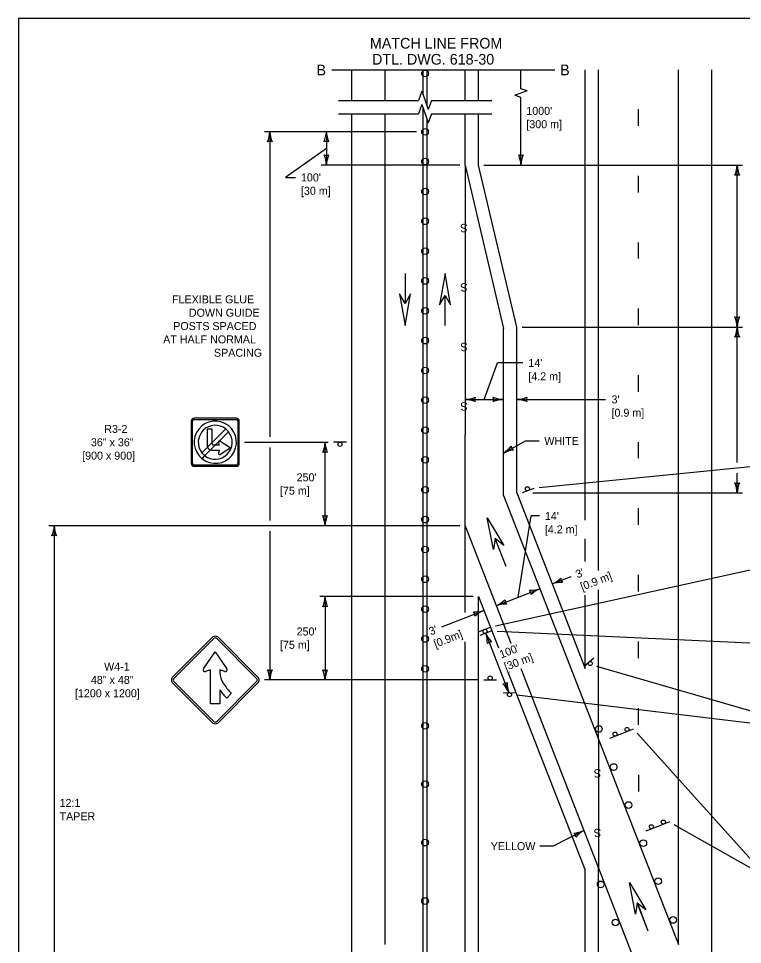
# Model space of a CAD drawing. Extents: x 49991.4 to 50021, y 49987.6 to 50011.4.
# Drawn here: x 50000.34 to 50005.76, y 50004.32 to 50011.26 of the extents above; entities that cross this region are included whole.
import ezdxf

# ---------------------------------------------------------------- set-up
doc = ezdxf.new("R2010")
doc.units = 0
for name, color, linetype in [('Level 1', 7, 'Continuous'), ('Level 2', 7, 'Continuous'), ('Level 3', 7, 'Continuous'), ('Level 6', 7, 'Continuous')]:
    doc.layers.add(name, color=color, linetype=linetype)

msp = doc.modelspace()

# ---------------------------------------------------------------- linework, layer by layer
at = {"layer": 'Level 1'}
for p, q in [((50002.8337, 50010.6493), (50002.8337, 50010.8774)), ((50003.0837, 50010.6493), (50003.0837, 50010.8774)), ((50003.3688, 50010.6919), (50003.3688, 50010.8773)), ((50003.3988, 50010.6067), (50003.3988, 50010.8773)), ((50003.6838, 50010.6493), (50003.6838, 50010.8773)), ((50003.7838, 50010.6493), (50003.7838, 50010.8773)), ((50004.5838, 50007.5049), (50004.5838, 50010.8773)), ((50004.6837, 50007.1256), (50004.6837, 50010.8774)), ((50005.2837, 50004.324), (50005.2837, 50010.8774)), ((50005.5337, 50003.9574), (50005.5337, 50010.8774)), ((50003.3688, 50002.0911), (50003.3688, 50010.5919)), ((50004.9837, 50010.4593), (50004.9837, 50010.5843)), ((50002.8337, 50003.9575), (50002.8337, 50010.5493)), ((50003.0837, 50004.324), (50003.0837, 50010.5493)), ((50003.3988, 50002.0911), (50003.3988, 50010.5067)), ((50003.6838, 50010.1642), (50003.6838, 50010.5493)), ((50003.7838, 50010.1642), (50003.7838, 50010.5493)), ((50003.6838, 50010.1642), (50003.6838, 50008.1421)), ((50003.6838, 50010.1642), (50003.9712, 50008.9389)), ((50004.0712, 50008.9505), (50003.7838, 50010.1642)), ((50004.9837, 50009.9592), (50004.9837, 50010.0843)), ((50004.9837, 50009.4642), (50004.9837, 50009.5842)), ((50003.2337, 50009.3525), (50003.2337, 50009.1267)), ((50003.2339, 50009.3525), (50003.2339, 50009.1267)), ((50003.5336, 50008.9625), (50003.5336, 50009.1883)), ((50003.5338, 50008.9625), (50003.5338, 50009.1883)), ((50004.9837, 50008.9642), (50004.9837, 50009.0892)), ((50003.9712, 50007.6888), (50003.9712, 50008.9389)), ((50004.0712, 50007.7075), (50004.0712, 50008.9505)), ((50004.9837, 50008.4642), (50004.9837, 50008.5892)), ((50001.6305, 50008.2449), (50001.6305, 50007.93)), ((50001.6399, 50007.93), (50001.6399, 50008.2449)), ((50001.968, 50008.2674), (50001.653, 50008.2674)), ((50001.653, 50008.258), (50001.968, 50008.258)), ((50001.9811, 50008.2449), (50001.9811, 50007.9299)), ((50001.9905, 50007.9299), (50001.9905, 50008.2449)), ((50001.7104, 50008.0084), (50001.8894, 50008.1875)), ((50001.9106, 50008.1663), (50001.7316, 50007.9872)), ((50001.788, 50008.1849), (50001.7505, 50008.1849)), ((50001.7505, 50008.1849), (50001.7505, 50008.0614)), ((50001.788, 50008.0776), (50001.788, 50008.1849)), ((50001.8894, 50008.1875), (50001.9106, 50008.1663)), ((50001.8894, 50008.1875), (50001.9106, 50008.1663)), ((50001.8339, 50008.0868), (50001.8408, 50008.0649)), ((50001.923, 50008.0461), (50001.8449, 50008.0954)), ((50002.7937, 50008.0873), (50002.6977, 50008.0873)), ((50003.6838, 50006.8117), (50003.6838, 50008.1421)), ((50004.9837, 50007.9691), (50004.9837, 50008.0892)), ((50001.7316, 50007.9872), (50001.7104, 50008.0084)), ((50001.7316, 50007.9872), (50001.7104, 50008.0084)), ((50001.7845, 50008.0274), (50001.8408, 50008.0274)), ((50001.8408, 50008.0649), (50001.8007, 50008.0649)), ((50001.8408, 50008.0274), (50001.8339, 50008.0054)), ((50001.8449, 50007.9969), (50001.923, 50008.0461)), ((50001.7121, 50007.9639), (50001.7316, 50007.9872)), ((50001.7321, 50007.9868), (50001.7126, 50007.9635)), ((50001.8449, 50007.9969), (50001.8449, 50007.9969)), ((50001.6305, 50007.93), (50001.6399, 50007.93)), ((50001.6305, 50007.9299), (50001.6399, 50007.9299)), ((50001.6399, 50007.9299), (50001.6305, 50007.9299)), ((50001.968, 50007.9167), (50001.653, 50007.9167)), ((50001.653, 50007.9074), (50001.968, 50007.9074)), ((50004.2006, 50007.7421), (50004.1112, 50007.7075)), ((50003.9712, 50007.6888), (50005.2838, 50004.3238)), ((50004.0712, 50007.7075), (50004.5838, 50006.3931)), ((50004.9837, 50007.4692), (50004.9837, 50007.5941)), ((50003.6838, 50007.4623), (50004.0273, 50006.5815)), ((50003.9916, 50007.1565), (50003.9096, 50007.367)), ((50003.9918, 50007.1565), (50003.9098, 50007.3671)), ((50004.5838, 50007.194), (50004.5838, 50007.3649)), ((50004.9837, 50006.9691), (50004.9837, 50007.0942)), ((50004.6837, 50005.8621), (50004.6837, 50006.9812)), ((50003.7838, 50006.931), (50003.9339, 50006.5462)), ((50003.7838, 50002.0911), (50003.7838, 50006.931)), ((50004.5838, 50006.3931), (50004.5838, 50006.9423)), ((50003.7839, 50006.6673), (50003.8733, 50006.7019)), ((50001.7893, 50006.6262), (50001.4904, 50006.3273)), ((50001.7893, 50006.6262), (50001.7893, 50006.6262)), ((50002.1309, 50006.3273), (50001.832, 50006.6262)), ((50003.8837, 50006.6735), (50003.7943, 50006.6389)), ((50001.7993, 50006.6161), (50001.5004, 50006.3172)), ((50001.7993, 50006.6161), (50001.7993, 50006.6161)), ((50002.1207, 50006.3172), (50001.8219, 50006.6161)), ((50003.6838, 50002.0911), (50003.6838, 50006.593)), ((50004.9837, 50006.4691), (50004.9837, 50006.5941)), ((50001.7224, 50006.389), (50001.8106, 50006.5172)), ((50001.8106, 50006.5172), (50001.8988, 50006.389)), ((50004.5778, 50006.4097), (50004.65, 50006.4728)), ((50001.7754, 50006.3809), (50001.7376, 50006.3686)), ((50001.7754, 50006.1281), (50001.7754, 50006.3809)), ((50001.8836, 50006.3686), (50001.8457, 50006.3809)), ((50001.8457, 50006.3809), (50001.8458, 50006.3596)), ((50004.0064, 50006.3603), (50004.5838, 50004.8798)), ((50004.1009, 50006.393), (50005.2837, 50003.3608)), ((50001.4904, 50006.2845), (50001.7893, 50005.9856)), ((50001.5004, 50006.2947), (50001.7993, 50005.9958)), ((50001.8219, 50005.9958), (50002.1207, 50006.2947)), ((50001.832, 50005.9856), (50002.1309, 50006.2845)), ((50003.8238, 50006.306), (50003.9198, 50006.306)), ((50001.8458, 50006.2323), (50001.8458, 50006.1281)), ((50001.9309, 50006.2044), (50001.8965, 50006.17)), ((50003.9689, 50006.2103), (50004.0647, 50006.2122)), ((50001.8458, 50006.1281), (50001.7754, 50006.1281)), ((50004.9837, 50005.9711), (50004.9837, 50006.0941)), ((50004.8584, 50005.904), (50004.9478, 50005.9388)), ((50004.6837, 50005.8621), (50004.6838, 50004.8987)), ((50004.7689, 50005.8691), (50004.8584, 50005.904)), ((50004.9837, 50005.5961), (50004.9837, 50005.471)), ((50005.1305, 50005.2103), (50005.22, 50005.2452)), ((50005.0411, 50005.1754), (50005.1305, 50005.2103)), ((50004.6838, 50001.8518), (50004.6838, 50004.8987)), ((50004.5838, 50000.9624), (50004.5838, 50004.8798)), ((50005.0573, 50004.4244), (50004.9752, 50004.6349)), ((50005.0575, 50004.4245), (50004.9754, 50004.635))]:
    msp.add_line(p, q, dxfattribs=at)
for points in [[(50008.6146, 50011.2628), (50000.3356, 50011.2628), (50000.3356, 50000.0624), (50008.6146, 50000.0624)], [(50003.5756, 50009.1161), (50003.5338, 50009.3525), (50003.492, 50009.1161), (50003.5338, 50009.1881)], [(50003.1919, 50009.1989), (50003.2337, 50008.9625), (50003.2755, 50009.1989), (50003.2337, 50009.1269)], [(50003.8967, 50007.2845), (50003.8497, 50007.52), (50003.9746, 50007.3148), (50003.9096, 50007.3668)], [(50004.9623, 50004.5523), (50004.9154, 50004.7879), (50005.0403, 50004.5826), (50004.9752, 50004.6347)]]:
    msp.add_lwpolyline(points, close=True, dxfattribs=at)
msp.add_lwpolyline([(50001.8102, 50006.5166), (50001.8107, 50006.5171)], dxfattribs=at)
for centre, radius in [((50003.3838, 50010.8517), 0.025), ((50003.3838, 50010.4142), 0.025), ((50003.3838, 50010.1907), 0.025), ((50003.3838, 50009.9671), 0.025), ((50003.3838, 50009.7435), 0.025), ((50003.3838, 50009.52), 0.025), ((50003.3838, 50009.2964), 0.025), ((50003.3838, 50009.0729), 0.025), ((50003.3838, 50008.8493), 0.025), ((50003.3838, 50008.6257), 0.025), ((50003.3838, 50008.4022), 0.025), ((50003.3838, 50008.1786), 0.025), ((50002.7458, 50008.0721), 0.0152), ((50003.3838, 50007.9551), 0.025), ((50003.3838, 50007.7315), 0.025), ((50004.1506, 50007.739), 0.0152), ((50003.3838, 50007.5079), 0.025), ((50003.3838, 50007.2844), 0.025), ((50003.3838, 50007.0608), 0.025), ((50003.3838, 50006.8373), 0.025), ((50003.3838, 50006.6137), 0.025), ((50003.8339, 50006.6705), 0.0152), ((50003.8339, 50006.6705), 0.0152), ((50003.3838, 50006.3901), 0.025), ((50004.6236, 50006.4298), 0.0152), ((50003.8717, 50006.3211), 0.0152), ((50004.0169, 50006.1961), 0.0152), ((50003.3838, 50005.9623), 0.025), ((50004.6867, 50005.9388), 0.025), ((50004.898, 50005.9353), 0.0152), ((50004.8086, 50005.9004), 0.0152), ((50004.7979, 50005.6538), 0.025), ((50003.3838, 50005.5248), 0.025), ((50004.909, 50005.3687), 0.025), ((50005.1702, 50005.2415), 0.0152), ((50005.0807, 50005.2066), 0.0152), ((50003.3838, 50005.0873), 0.025), ((50005.0202, 50005.0837), 0.025), ((50005.1314, 50004.7987), 0.025), ((50004.7005, 50004.7745), 0.025), ((50003.3838, 50004.6498), 0.025), ((50004.8117, 50004.4894), 0.025), ((50005.2442, 50004.5079), 0.025)]:
    msp.add_circle(centre, radius, dxfattribs=at)
for centre, radius, start, end in [((50001.6531, 50008.2448), 0.0225, 90, 180), ((50001.6531, 50008.2448), 0.0131, 90, 180), ((50001.811, 50008.0878), 0.1585, 231.65928, 231.42697), ((50001.8106, 50008.0873), 0.1275, 51.75713, 218.2435), ((50001.9681, 50008.2448), 0.0225, 0, 90), ((50001.9681, 50008.2448), 0.0131, 0, 90), ((50001.8106, 50008.0873), 0.1275, 139.12855, 139.14364), ((50001.8106, 50008.0873), 0.1275, 232.04534, 38.24287), ((50001.8008, 50008.0776), 0.0128, 180, 270), ((50001.841, 50008.089), 0.00742, 57.75616, 197.61961), ((50001.7846, 50008.0613), 0.034, 180, 270), ((50001.841, 50008.0031), 0.00742, 162.38136, 302.24299), ((50001.8106, 50008.0873), 0.1275, 315.58365, 315.71312), ((50001.6531, 50007.9298), 0.0225, 180, 270), ((50001.6531, 50007.9298), 0.0131, 180, 270), ((50001.9681, 50007.9298), 0.0225, 270, 0), ((50001.9681, 50007.9298), 0.0131, 270, 0), ((50001.8106, 50006.6048), 0.0302, 45.00008, 134.99993), ((50001.8106, 50006.6048), 0.0159, 45.00008, 134.99993), ((50001.7334, 50006.3814), 0.0134, 145.48059, 287.95818), ((50001.975, 50006.3596), 0.1292, 180, 216.3165), ((50001.8878, 50006.3814), 0.0134, 252.04182, 34.51941), ((50001.5117, 50006.3059), 0.0302, 134.99993, 225.00008), ((50001.5117, 50006.3059), 0.0159, 134.99993, 225.00008), ((50002.2576, 50006.5156), 0.4512, 211.01433, 223.6035), ((50002.1095, 50006.3059), 0.0159, 314.99993, 45.00007), ((50002.1095, 50006.3059), 0.0302, 314.99993, 45.00008), ((50002.2576, 50006.5156), 0.4999, 214.53029, 223.73943), ((50001.8106, 50006.007), 0.0159, 225.00007, 314.99993), ((50001.8106, 50006.007), 0.0302, 225.00007, 314.99993)]:
    msp.add_arc(centre, radius, start, end, dxfattribs=at)
at = {"layer": 'Level 3'}
for p, q in [((50004.1029, 50010.7364), (50004.1029, 50010.8773)), ((50004.1487, 50010.7202), (50004.1029, 50010.7364)), ((50004.1487, 50010.7202), (50004.1029, 50010.704)), ((50004.1029, 50010.704), (50004.0573, 50010.6878)), ((50004.1029, 50010.6716), (50004.0573, 50010.6878)), ((50004.1029, 50010.1642), (50004.1029, 50010.6716)), ((50003.3188, 50010.4142), (50002.1797, 50010.4142)), ((50002.2197, 50010.4142), (50002.2197, 50008.1273)), ((50002.6437, 50010.4142), (50002.6437, 50010.1642)), ((50003.6438, 50010.1642), (50002.6037, 50010.1642)), ((50003.8238, 50010.1642), (50005.7637, 50010.1642)), ((50005.7237, 50008.9505), (50005.7237, 50010.1642)), ((50004.1112, 50008.9505), (50005.7637, 50008.9505)), ((50005.7237, 50007.9368), (50005.7237, 50008.9505)), ((50003.8275, 50008.4088), (50003.9267, 50008.6816)), ((50004.1181, 50008.6816), (50003.9267, 50008.6816)), ((50003.6838, 50008.4088), (50003.9712, 50008.4088)), ((50004.0712, 50008.4088), (50004.7357, 50008.4088)), ((50002.0306, 50008.0874), (50002.6577, 50008.0873)), ((50002.6337, 50007.4623), (50002.6337, 50008.0873)), ((50003.9712, 50008.0066), (50004.1381, 50008.0972)), ((50004.1381, 50008.0972), (50004.2381, 50008.0972)), ((50002.2197, 50008.0473), (50002.2197, 50007.5023)), ((50004.2401, 50007.7482), (50006.2164, 50007.9462)), ((50005.7237, 50007.7075), (50005.7237, 50007.8568)), ((50004.1912, 50007.7075), (50005.7637, 50007.7075)), ((50004.0808, 50006.9261), (50004.1796, 50007.5349)), ((50004.2422, 50007.5349), (50004.1796, 50007.5349)), ((50003.6438, 50007.4623), (50000.5634, 50007.4623)), ((50000.6034, 50007.4623), (50000.6034, 50003.3608)), ((50002.2197, 50007.4223), (50002.2197, 50006.306)), ((50003.9122, 50006.711), (50006.3662, 50007.2512)), ((50004.3366, 50007.0256), (50004.4782, 50007.0806)), ((50003.9177, 50006.8627), (50004.2438, 50006.9895)), ((50003.7438, 50006.931), (50002.5937, 50006.931)), ((50002.6337, 50006.931), (50002.6337, 50006.306)), ((50003.5087, 50006.7036), (50003.8244, 50006.8264)), ((50004.0112, 50006.2111), (50003.8392, 50006.6563)), ((50003.9236, 50006.6717), (50006.2162, 50006.5656)), ((50006.3646, 50005.917), (50004.6718, 50006.4062)), ((50003.7838, 50006.306), (50002.1797, 50006.306)), ((50006.3646, 50005.917), (50004.0718, 50006.1913)), ((50005.9453, 50004.8292), (50004.9734, 50005.9081)), ((50004.5743, 50005.1792), (50004.3446, 50005.0608)), ((50005.9453, 50004.8292), (50005.2517, 50005.2208)), ((50004.3446, 50005.0608), (50004.2446, 50005.0608))]:
    msp.add_line(p, q, dxfattribs=at)
msp.add_lwpolyline([(50002.6437, 50010.2892), (50002.3386, 50010.072), (50002.4134, 50010.072)], dxfattribs=at)
for centre, radius, start, end in [((50001.987, 50010.4257), 0.233, 337.92284, 357.17269), ((50002.4418, 50010.4234), 0.2223, 182.36048, 202.54399), ((50002.411, 50010.4257), 0.233, 337.92284, 357.17269), ((50002.8658, 50010.4234), 0.2223, 182.36048, 202.54399), ((50002.2197, 50010.286), 0.0548, 72.13882, 107.86118), ((50002.6437, 50010.286), 0.0548, 72.13882, 107.86118), ((50002.4216, 50010.155), 0.2223, 2.36048, 22.54399), ((50002.6437, 50010.2924), 0.0548, 252.13882, 287.86118), ((50002.8764, 50010.1527), 0.233, 157.92284, 177.17269), ((50004.1029, 50010.2925), 0.0548, 252.13882, 287.86118), ((50003.8702, 50010.1527), 0.233, 2.82731, 22.07716), ((50004.325, 50010.1551), 0.2223, 157.45601, 177.63952), ((50005.491, 50010.1757), 0.233, 337.92284, 357.17269), ((50005.9458, 50010.1734), 0.2223, 182.36048, 202.54399), ((50005.7237, 50010.036), 0.0548, 72.13882, 107.86118), ((50005.5016, 50008.9414), 0.2223, 2.36048, 22.54399), ((50005.7237, 50009.0788), 0.0548, 252.13882, 287.86118), ((50005.9564, 50008.939), 0.233, 157.92284, 177.17269), ((50005.491, 50008.962), 0.233, 337.92284, 357.17269), ((50005.9458, 50008.9597), 0.2223, 182.36048, 202.54399), ((50005.7237, 50008.8223), 0.0548, 72.13882, 107.86118), ((50003.6723, 50008.6415), 0.233, 272.82731, 292.07716), ((50003.812, 50008.4088), 0.0548, 162.13882, 197.86118), ((50003.843, 50008.4088), 0.0548, 342.13882, 17.86118), ((50003.9827, 50008.6415), 0.233, 247.92284, 267.17269), ((50004.0597, 50008.6415), 0.233, 272.82731, 292.07716), ((50004.1994, 50008.4088), 0.0548, 162.13882, 197.86118), ((50003.6746, 50008.1867), 0.2223, 67.45601, 87.63952), ((50003.9803, 50008.1867), 0.2223, 92.36048, 112.54399), ((50004.062, 50008.1867), 0.2223, 67.45601, 87.63952), ((50002.4116, 50008.0965), 0.2223, 337.45601, 357.63952), ((50002.8664, 50008.0988), 0.233, 182.82731, 202.07716), ((50002.6337, 50007.9591), 0.0548, 72.13882, 107.86118), ((50003.8501, 50008.2056), 0.233, 301.32055, 320.5704), ((50004.0691, 50007.807), 0.2223, 95.94925, 116.13275), ((50004.0839, 50008.0677), 0.0548, 190.63205, 226.35442), ((50005.5016, 50007.6983), 0.2223, 2.36048, 22.54399), ((50005.7237, 50007.8357), 0.0548, 252.13882, 287.86118), ((50005.9564, 50007.696), 0.233, 157.92284, 177.17269), ((50002.6337, 50007.5905), 0.0548, 252.13882, 287.86118), ((50002.401, 50007.4508), 0.233, 2.82731, 22.07716), ((50002.8558, 50007.4531), 0.2223, 157.45601, 177.63952), ((50000.3813, 50007.4715), 0.2223, 337.45601, 357.63952), ((50000.8362, 50007.4738), 0.233, 182.82731, 202.07716), ((50000.6034, 50007.3341), 0.0548, 72.13882, 107.86118), ((50004.2413, 50007.2382), 0.233, 294.13681, 313.38666), ((50004.4088, 50006.8153), 0.2223, 88.76551, 108.94902), ((50004.456, 50007.0722), 0.0548, 183.44832, 219.17068), ((50004.1733, 50007.2116), 0.233, 268.36713, 287.61698), ((50004.1237, 50006.9447), 0.0548, 2.58311, 38.30547), ((50004.33, 50006.7846), 0.2223, 112.80477, 132.98828), ((50002.4116, 50006.9402), 0.2223, 337.45601, 357.63952), ((50002.8664, 50006.9425), 0.233, 182.82731, 202.07716), ((50003.8224, 50007.0753), 0.233, 294.13681, 313.38666), ((50004.0371, 50006.9093), 0.0548, 183.44832, 219.17068), ((50002.6337, 50006.8028), 0.0548, 72.13882, 107.86118), ((50003.7539, 50007.0485), 0.233, 268.36713, 287.61698), ((50003.9105, 50006.6215), 0.2223, 112.80477, 132.98828), ((50003.9899, 50006.6524), 0.2223, 88.76551, 108.94902), ((50003.7042, 50006.7816), 0.0548, 2.58311, 38.30547), ((50003.6287, 50006.5847), 0.2223, 358.5793, 18.76281), ((50004.0522, 50006.7508), 0.233, 203.9506, 223.20045), ((50003.8854, 50006.5367), 0.0548, 93.26211, 128.98447), ((50002.2197, 50006.4342), 0.0548, 252.13882, 287.86118), ((50001.987, 50006.2945), 0.233, 2.82731, 22.07716), ((50002.4418, 50006.2968), 0.2223, 157.45601, 177.63952), ((50002.6337, 50006.4342), 0.0548, 252.13882, 287.86118), ((50002.401, 50006.2945), 0.233, 2.82731, 22.07716), ((50002.8558, 50006.2968), 0.2223, 157.45601, 177.63952), ((50003.965, 50006.3307), 0.0548, 273.26211, 308.98447), ((50003.7983, 50006.1166), 0.233, 23.9506, 43.20045), ((50004.2217, 50006.2826), 0.2223, 178.5793, 198.76281), ((50004.4807, 50005.3809), 0.2223, 274.71612, 294.89963), ((50004.4604, 50005.1205), 0.0548, 9.39893, 45.12129), ((50004.6912, 50004.9776), 0.233, 120.08742, 139.33727)]:
    msp.add_arc(centre, radius, start, end, dxfattribs=at)
at = {"layer": 'Level 6'}
for p, q in [((50002.6837, 50010.8773), (50004.3568, 50010.8773)), ((50003.3596, 50010.7177), (50003.3352, 50010.6493)), ((50003.3596, 50010.7177), (50003.3838, 50010.6493)), ((50002.7337, 50010.6493), (50003.3352, 50010.6493)), ((50003.3838, 50010.6493), (50003.408, 50010.5805)), ((50003.4324, 50010.6493), (50003.408, 50010.5805)), ((50003.4324, 50010.6493), (50003.8838, 50010.6493)), ((50003.3596, 50010.6177), (50003.3352, 50010.5493)), ((50003.3596, 50010.6177), (50003.3838, 50010.5493)), ((50002.7337, 50010.5493), (50003.3352, 50010.5493)), ((50003.3838, 50010.5493), (50003.408, 50010.4805)), ((50003.4324, 50010.5493), (50003.408, 50010.4805)), ((50003.4324, 50010.5493), (50003.8838, 50010.5493))]:
    msp.add_line(p, q, dxfattribs=at)

# ---------------------------------------------------------------- texts
at = {"layer": 'Level 1'}
for p in [(50003.7028, 50009.7238), (50003.7032, 50009.279), (50003.704, 50008.8328), (50003.704, 50008.3866), (50004.7046, 50005.6375), (50004.7046, 50005.1913)]:
    msp.add_text('S', height=0.0625, rotation=180, dxfattribs=at).set_placement(p)
at = {"layer": 'Level 2'}
for s, height, p in [('MATCH LINE FROM', 0.08, (50002.9706, 50011.0373)), ('DTL. DWG. 618-30', 0.08, (50002.9866, 50010.9173)), ('B', 0.08, (50002.5697, 50010.8373)), ('B', 0.08, (50004.3968, 50010.8373)), ("1000'", 0.06, (50004.1429, 50010.5408)), ('[300 m]', 0.06, (50004.1429, 50010.4408)), ("100'", 0.06, (50002.4534, 50010.042)), ('[30 m]', 0.06, (50002.4534, 50009.942)), ("14'", 0.06, (50004.1581, 50008.6516)), ('[4.2 m]', 0.06, (50004.1581, 50008.5516)), ("3'", 0.06, (50004.7819, 50008.3788)), ('[0.9 m]', 0.06, (50004.7819, 50008.2788)), ('R3-2', 0.06, (50000.9785, 50008.1573)), ('36" x 36"', 0.06, (50000.8784, 50008.0573)), ('WHITE', 0.06, (50004.2781, 50008.0672)), ('[900 x 900]', 0.06, (50000.8128, 50007.9573)), ("250'", 0.06, (50002.4209, 50007.7948)), ('[75 m]', 0.06, (50002.296, 50007.6948)), ("250'", 0.06, (50002.4209, 50006.6396)), ('[75 m]', 0.06, (50002.296, 50006.5396)), ('W4-1', 0.06, (50000.9776, 50006.3766)), ('48" x 48"', 0.06, (50000.8784, 50006.2766)), ('[1200 x 1200]', 0.06, (50000.7589, 50006.1766)), ('12:1', 0.06, (50000.6435, 50005.3546)), ('TAPER', 0.06, (50000.6435, 50005.2546)), ('YELLOW', 0.06, (50003.8764, 50005.0308))]:
    msp.add_text(s, height=height, dxfattribs=at).set_placement(p)
for s, rotation, p in [('FLEXIBLE GLUE', 0.0174, (50001.4869, 50009.1281)), ('DOWN GUIDE', 0.0174, (50001.6129, 50009.0281)), ('POSTS SPACED', 0.0174, (50001.4956, 50008.9281)), ('AT HALF NORMAL', 0.0174, (50001.4201, 50008.8281)), ('SPACING', 0.0174, (50001.8009, 50008.7282)), ("14'", 0, (50004.2822, 50007.5049)), ('[4.2 m]', 0, (50004.2822, 50007.4049)), ("3'", 21.3095, (50004.5264, 50007.0672)), ('[0.9 m]', 21.3095, (50004.5627, 50006.974)), ("3'", 21.3095, (50003.4264, 50006.6394)), ('[0.9m]', 21.3095, (50003.4627, 50006.5462)), ("100'", 21.12329, (50003.9553, 50006.4668)), ('[30 m]', 21.12329, (50003.9913, 50006.3735))]:
    msp.add_text(s, height=0.06, rotation=rotation, dxfattribs=at).set_placement(p)

doc.saveas('drawing.dxf')
